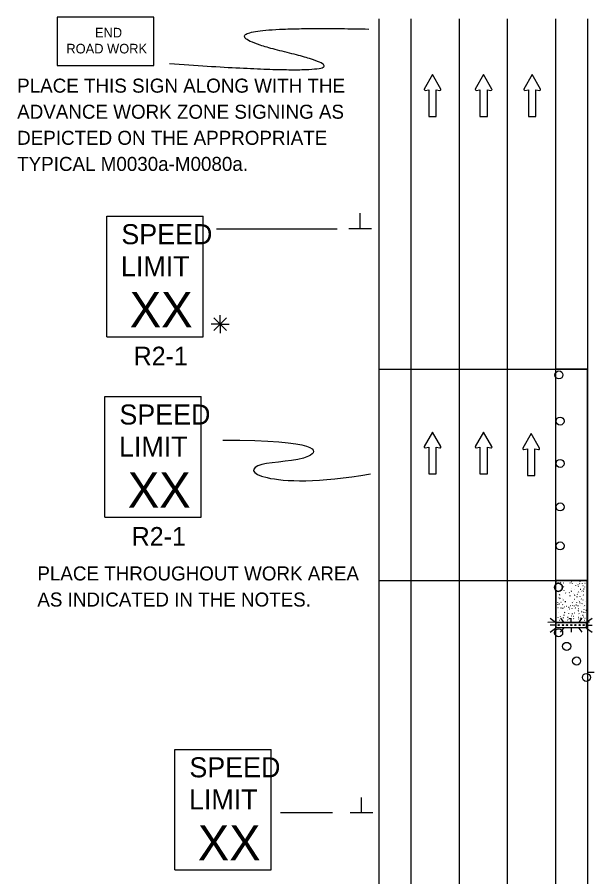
# Model space of a CAD drawing. Extents: x 16741 to 18479, y 6916 to 8211.
# Drawn here: x 16740.9 to 17027.6, y 7781.4 to 8209.8 of the extents above; entities that cross this region are included whole.
import ezdxf

# ---------------------------------------------------------------- set-up
doc = ezdxf.new("R2010")
doc.units = 0
for name, color, linetype in [('ALI_LEGAL_EX', 7, 'Continuous'), ('MT_SCRATCH_LEVEL_E', 7, 'Continuous'), ('PAVT_EDGE_EX', 7, 'Continuous'), ('TRAFFIC_SIGNS_PR', 7, 'Continuous'), ('TYPICAL_TEXT_DIMEN_PR', 7, 'Continuous')]:
    doc.layers.add(name, color=color, linetype=linetype)

msp = doc.modelspace()

# ---------------------------------------------------------------- linework, layer by layer
at = {"layer": 'ALI_LEGAL_EX'}
for p, q in [((16960.92, 8208.99), (16960.92, 7455.58)), ((16984.92, 8208.99), (16984.92, 7455.58))]:
    msp.add_line(p, q, dxfattribs=at)
for points in [[(16960.92, 8208.99), (16960.92, 8183.99)], [(16960.92, 8208.99), (16960.92, 8183.99)], [(16984.92, 8208.99), (16984.92, 8183.99)], [(16960.92, 8107.36), (16960.92, 8082.36)], [(16984.92, 8107.36), (16984.92, 8082.36)], [(16960.92, 8007.36), (16960.92, 7982.36)], [(16984.92, 8007.36), (16984.92, 7982.36)], [(16960.92, 7907.36), (16960.92, 7882.36)], [(16984.92, 7907.36), (16984.92, 7882.36)], [(16960.92, 7807.36), (16960.92, 7782.36)], [(16984.92, 7807.36), (16984.92, 7782.36)]]:
    msp.add_lwpolyline(points, dxfattribs=at)
at = {"layer": 'MT_SCRATCH_LEVEL_E'}
for p, q in [((16947.72, 8181.2), (16943.61, 8173.96)), ((16947.72, 8181.2), (16943.61, 8173.96)), ((16951.87, 8173.96), (16947.72, 8181.2)), ((16951.87, 8173.96), (16947.72, 8181.2)), ((16973.15, 8181.2), (16969.04, 8173.96)), ((16973.15, 8181.2), (16969.04, 8173.96)), ((16977.3, 8173.96), (16973.15, 8181.2)), ((16977.3, 8173.96), (16973.15, 8181.2)), ((16997.36, 8181.2), (16993.25, 8173.96)), ((16997.36, 8181.2), (16993.25, 8173.96)), ((17001.51, 8173.96), (16997.36, 8181.2)), ((17001.51, 8173.96), (16997.36, 8181.2)), ((16944.1, 8173.28), (16945.87, 8173.59)), ((16944.1, 8173.28), (16945.87, 8173.59)), ((16945.87, 8173.59), (16945.87, 8160.34)), ((16945.87, 8173.59), (16945.87, 8160.34)), ((16949.61, 8160.34), (16949.61, 8173.59)), ((16949.61, 8173.59), (16951.39, 8173.28)), ((16949.61, 8160.34), (16949.61, 8173.59)), ((16949.61, 8173.59), (16951.39, 8173.28)), ((16969.52, 8173.28), (16971.3, 8173.59)), ((16969.52, 8173.28), (16971.3, 8173.59)), ((16971.3, 8173.59), (16971.3, 8160.34)), ((16971.3, 8173.59), (16971.3, 8160.34)), ((16975.04, 8160.34), (16975.04, 8173.59)), ((16975.04, 8173.59), (16976.82, 8173.28)), ((16975.04, 8160.34), (16975.04, 8173.59)), ((16975.04, 8173.59), (16976.82, 8173.28)), ((16993.73, 8173.28), (16995.51, 8173.59)), ((16993.73, 8173.28), (16995.51, 8173.59)), ((16995.51, 8173.59), (16995.51, 8160.34)), ((16995.51, 8173.59), (16995.51, 8160.34)), ((16999.25, 8160.34), (16999.25, 8173.59)), ((16999.25, 8173.59), (17001.03, 8173.28)), ((16999.25, 8160.34), (16999.25, 8173.59)), ((16999.25, 8173.59), (17001.03, 8173.28)), ((16945.87, 8160.34), (16949.61, 8160.34)), ((16945.87, 8160.34), (16949.61, 8160.34)), ((16971.3, 8160.34), (16975.04, 8160.34)), ((16971.3, 8160.34), (16975.04, 8160.34)), ((16995.51, 8160.34), (16999.25, 8160.34)), ((16995.51, 8160.34), (16999.25, 8160.34)), ((16947.72, 8003.02), (16943.61, 7995.78)), ((16947.72, 8003.02), (16943.61, 7995.78)), ((16951.87, 7995.78), (16947.72, 8003.02)), ((16951.87, 7995.78), (16947.72, 8003.02)), ((16973.15, 8003.02), (16969.04, 7995.78)), ((16973.15, 8003.02), (16969.04, 7995.78)), ((16977.3, 7995.78), (16973.15, 8003.02)), ((16977.3, 7995.78), (16973.15, 8003.02)), ((16996.85, 8002.28), (16992.74, 7995.04)), ((16996.85, 8002.28), (16992.74, 7995.04)), ((17001, 7995.04), (16996.85, 8002.28)), ((17001, 7995.04), (16996.85, 8002.28)), ((16944.1, 7995.1), (16945.87, 7995.41)), ((16944.1, 7995.1), (16945.87, 7995.41)), ((16945.87, 7995.41), (16945.87, 7982.15)), ((16945.87, 7995.41), (16945.87, 7982.15)), ((16949.61, 7982.15), (16949.61, 7995.41)), ((16949.61, 7995.41), (16951.39, 7995.1)), ((16949.61, 7982.15), (16949.61, 7995.41)), ((16949.61, 7995.41), (16951.39, 7995.1)), ((16969.52, 7995.1), (16971.3, 7995.41)), ((16969.52, 7995.1), (16971.3, 7995.41)), ((16971.3, 7995.41), (16971.3, 7982.15)), ((16971.3, 7995.41), (16971.3, 7982.15)), ((16975.04, 7982.15), (16975.04, 7995.41)), ((16975.04, 7995.41), (16976.82, 7995.1)), ((16975.04, 7982.15), (16975.04, 7995.41)), ((16975.04, 7995.41), (16976.82, 7995.1)), ((16993.22, 7994.36), (16995, 7994.68)), ((16993.22, 7994.36), (16995, 7994.68)), ((16995, 7994.68), (16995, 7981.42)), ((16995, 7994.68), (16995, 7981.42)), ((16998.74, 7981.42), (16998.74, 7994.68)), ((16998.74, 7994.68), (17000.52, 7994.36)), ((16998.74, 7981.42), (16998.74, 7994.68)), ((16998.74, 7994.68), (17000.52, 7994.36)), ((16945.87, 7982.15), (16949.61, 7982.15)), ((16945.87, 7982.15), (16949.61, 7982.15)), ((16971.3, 7982.15), (16975.04, 7982.15)), ((16971.3, 7982.15), (16975.04, 7982.15)), ((16995, 7981.42), (16998.74, 7981.42)), ((16995, 7981.42), (16998.74, 7981.42))]:
    msp.add_line(p, q, dxfattribs=at)
for centre, start, end in [((16944.02, 8173.74), 150.4248, 279.9638), ((16944.02, 8173.74), 150.4248, 279.9638), ((16951.46, 8173.74), 260.0362, 29.7731), ((16951.46, 8173.74), 260.0362, 29.7731), ((16969.45, 8173.74), 150.4248, 279.9638), ((16969.45, 8173.74), 150.4248, 279.9638), ((16976.89, 8173.74), 260.0362, 29.7731), ((16976.89, 8173.74), 260.0362, 29.7731), ((16993.66, 8173.74), 150.4248, 279.9638), ((16993.66, 8173.74), 150.4248, 279.9638), ((17001.1, 8173.74), 260.0362, 29.7731), ((17001.1, 8173.74), 260.0362, 29.7731), ((16944.02, 7995.55), 150.4248, 279.9638), ((16944.02, 7995.55), 150.4248, 279.9638), ((16951.46, 7995.56), 260.0362, 29.7731), ((16951.46, 7995.56), 260.0362, 29.7731), ((16969.45, 7995.55), 150.4248, 279.9638), ((16969.45, 7995.55), 150.4248, 279.9638), ((16976.89, 7995.56), 260.0362, 29.7731), ((16976.89, 7995.56), 260.0362, 29.7731), ((16993.15, 7994.82), 150.4248, 279.9638), ((16993.15, 7994.82), 150.4248, 279.9638), ((17000.59, 7994.82), 260.0362, 29.7731), ((17000.59, 7994.82), 260.0362, 29.7731)]:
    msp.add_arc(centre, 0.463, start, end, dxfattribs=at)
at = {"layer": 'PAVT_EDGE_EX'}
for p, q in [((16920.92, 8208.99), (16920.92, 7354.26)), ((16936.92, 8208.99), (16936.92, 7354.26)), ((17008.92, 8208.99), (17008.92, 7354.26)), ((17024.92, 8208.99), (17024.92, 7354.26)), ((16921.45, 8034.32), (17024.92, 8034.32)), ((17024.92, 8034.32), (17008.92, 8034.32)), ((17008.92, 8034.32), (17008.92, 7929.01)), ((17024.92, 8034.32), (17008.92, 8034.32)), ((17008.92, 8034.32), (17008.92, 7929.01)), ((17024.92, 7929.01), (17024.92, 8034.32)), ((17024.92, 7929.01), (17024.92, 8034.32)), ((16921.45, 7929.01), (17024.92, 7929.01)), ((17008.92, 7929.01), (17024.92, 7929.01)), ((17008.92, 7929.01), (17024.92, 7929.01)), ((17028.22, 7883.18), (17024.92, 7883.18))]:
    msp.add_line(p, q, dxfattribs=at)
at = {"layer": 'TRAFFIC_SIGNS_PR'}
for p, q in [((16785.52, 8110.54), (16833.52, 8110.54)), ((16785.52, 8050.54), (16785.52, 8110.54)), ((16833.52, 8050.54), (16833.52, 8110.54)), ((16785.52, 8050.54), (16833.52, 8050.54)), ((16784.56, 8020.67), (16832.56, 8020.67)), ((16784.56, 7960.67), (16784.56, 8020.67)), ((16832.56, 7960.67), (16832.56, 8020.67)), ((16784.56, 7960.67), (16832.56, 7960.67)), ((17024.79, 7929.01), (17009.1, 7929.01)), ((17024.79, 7929.01), (17009.1, 7929.01)), ((17024.79, 7929.01), (17009.1, 7929.01)), ((17006.34, 7910.26), (17009.04, 7908.26)), ((17013.12, 7908.26), (17011.56, 7910.27)), ((17016.76, 7908.26), (17016.76, 7910.27)), ((17020.71, 7908.26), (17022.27, 7910.27)), ((17024.49, 7908.26), (17027.18, 7910.27)), ((17024.61, 7908.35), (17024.79, 7908.48)), ((17024.61, 7908.35), (17024.79, 7908.48)), ((17024.61, 7908.35), (17024.79, 7908.48)), ((17009.04, 7906.81), (17006.34, 7906.81)), ((17006.34, 7903.35), (17009.04, 7905.36)), ((17010.6, 7906.81), (17010.6, 7906.81)), ((17011.54, 7903.35), (17013.09, 7905.36)), ((17012.68, 7906.81), (17012.68, 7906.81)), ((17014.76, 7906.81), (17014.76, 7906.81)), ((17016.76, 7905.36), (17016.76, 7903.35)), ((17016.83, 7906.81), (17016.83, 7906.81)), ((17018.91, 7906.81), (17018.91, 7906.81)), ((17022.29, 7903.35), (17020.74, 7905.36)), ((17020.99, 7906.81), (17020.99, 7906.81)), ((17023.06, 7906.81), (17023.06, 7906.81)), ((17024.49, 7906.81), (17027.18, 7906.81)), ((17024.49, 7905.36), (17027.18, 7903.35)), ((16819.42, 7844.86), (16867.42, 7844.86)), ((16819.42, 7784.86), (16819.42, 7844.86)), ((16867.42, 7784.86), (16867.42, 7844.86)), ((16819.42, 7784.86), (16867.42, 7784.86))]:
    msp.add_line(p, q, dxfattribs=at)
for points in [[(16760.83, 8185.76), (16808.83, 8185.76), (16808.83, 8209.76), (16760.83, 8209.76)], [(17024.27, 7905.52), (17009.26, 7905.52), (17009.26, 7908.09), (17024.27, 7908.09)]]:
    msp.add_lwpolyline(points, close=True, dxfattribs=at)
for points in [[(17009.1, 7929.01), (17009.1, 7927.13)], [(17009.1, 7929.01), (17009.1, 7927.13)], [(17009.1, 7929.01), (17009.1, 7927.13)], [(17024.79, 7908.48), (17024.79, 7929.01)], [(17024.79, 7908.48), (17024.79, 7929.01)], [(17024.79, 7908.48), (17024.79, 7929.01)], [(17009.1, 7924.12), (17009.1, 7908.35), (17024.61, 7908.35)], [(17009.1, 7924.12), (17009.1, 7908.35), (17024.61, 7908.35)], [(17009.1, 7924.12), (17009.1, 7908.35)], [(17009.1, 7908.35), (17024.61, 7908.35)]]:
    msp.add_lwpolyline(points, dxfattribs=at)
for centre in [(17010.68, 8031.49), (17011.28, 8008.44), (17011.28, 7987.35), (17011.28, 7965.7), (17011.28, 7946.3), (17010.41, 7925.63), (17010.54, 7902.98), (17014.54, 7896.21), (17019.48, 7888.91), (17024.38, 7880.75)]:
    msp.add_circle(centre, 2, dxfattribs=at)
for start, end in [(43.6951, 131.0724), (43.6961, 131.0724), (43.6971, 131.0724), (0, 43.6931), (0.0007, 43.6931), (0.0007, 43.6931), (316.3077, 0), (316.3084, 0), (316.3084, 0), (228.9207, 316.3069), (228.9207, 316.3069), (228.9207, 316.3069), (228.9198, 240), (228.9207, 240.0001)]:
    msp.add_arc((17010.41, 7925.63), 2, start, end, dxfattribs=at)
for centre in [(17010.62, 7906.81), (17012.68, 7906.81), (17014.76, 7906.81), (17016.83, 7906.81), (17018.91, 7906.81), (17020.99, 7906.81), (17023.06, 7906.81)]:
    msp.add_ellipse(centre, major_axis=(0.362, 0), ratio=0.745879, dxfattribs=at)
msp.add_open_spline([(16816.7, 8186.66), (16931.92, 8178.42), (16818.01, 8206), (16915.96, 8203.84)], degree=2, dxfattribs=at)
at = {"layer": 'TYPICAL_TEXT_DIMEN_PR'}
for p, q in [((16911.63, 8104.3), (16911.63, 8112.08)), ((16840.05, 8104.31), (16900.3, 8104.31)), ((16911.63, 8104.3), (16906.01, 8104.3)), ((16917.26, 8104.3), (16911.63, 8104.3)), ((16838.77, 8059.95), (16845.15, 8053.57)), ((16845.15, 8059.95), (16838.77, 8053.57)), ((16841.96, 8056.76), (16841.96, 8061.22)), ((16841.96, 8056.76), (16837.43, 8056.76)), ((16841.96, 8056.76), (16845.15, 8056.76)), ((16841.96, 8056.76), (16846.44, 8056.76)), ((16841.96, 8056.76), (16841.96, 8052.26)), ((17024.79, 7929.01), (17009.1, 7929.01)), ((17010.06, 7928.08), (17010.27, 7928.03)), ((17011.47, 7928.14), (17011.68, 7928.08)), ((17011.57, 7927.22), (17011.52, 7927.32)), ((17011.95, 7927.68), (17011.9, 7927.78)), ((17012.98, 7927.88), (17013.2, 7927.83)), ((17013.04, 7925.94), (17012.98, 7926.05)), ((17016.24, 7927.68), (17016.18, 7927.78)), ((17016.78, 7925.13), (17016.72, 7925.23)), ((17016.78, 7928.29), (17017, 7928.24)), ((17017.43, 7927.57), (17017.38, 7927.68)), ((17019.16, 7926.45), (17019.11, 7926.56)), ((17019.6, 7927.68), (17019.54, 7927.78)), ((17020.09, 7927.01), (17020.3, 7926.96)), ((17020.36, 7926.1), (17020.3, 7926.2)), ((17021.01, 7927.42), (17020.95, 7927.52)), ((17021.12, 7928.49), (17021.33, 7928.44)), ((17022.42, 7927.62), (17022.36, 7927.73)), ((17022.53, 7926.56), (17022.74, 7926.5)), ((17023.5, 7927.73), (17023.72, 7927.68)), ((17023.61, 7925.79), (17023.56, 7925.89)), ((17010.33, 7922.02), (17010.27, 7922.12)), ((17010.98, 7921.92), (17011.3, 7922.07)), ((17013.36, 7924.06), (17013.31, 7924.16)), ((17014.07, 7922.78), (17014.01, 7922.88)), ((17015.75, 7922.99), (17015.97, 7922.94)), ((17016.13, 7921.41), (17016.45, 7921.56)), ((17016.78, 7923.7), (17017.1, 7923.85)), ((17017.92, 7922.68), (17017.86, 7922.78)), ((17018.51, 7921.66), (17018.84, 7921.81)), ((17018.62, 7924.52), (17018.57, 7924.62)), ((17019.54, 7921), (17019.54, 7920.69)), ((17019.76, 7922.17), (17019.98, 7922.12)), ((17020.25, 7923.34), (17020.47, 7923.29)), ((17021.06, 7922.83), (17021.01, 7922.94)), ((17021.28, 7920.9), (17021.22, 7921)), ((17021.33, 7924.72), (17021.55, 7924.67)), ((17022.2, 7923.8), (17022.15, 7923.9)), ((17022.63, 7921.51), (17022.58, 7921.61)), ((17022.85, 7921.86), (17023.07, 7921.81)), ((17022.96, 7924.92), (17023.18, 7924.87)), ((17023.01, 7923.5), (17022.96, 7923.6)), ((17010.11, 7918.14), (17010.06, 7918.24)), ((17010.11, 7917.07), (17010.06, 7917.17)), ((17010.6, 7917.33), (17010.92, 7917.48)), ((17010.76, 7920.34), (17010.71, 7920.44)), ((17011.14, 7920.03), (17011.46, 7920.18)), ((17011.74, 7918.04), (17011.68, 7918.14)), ((17012.39, 7917.02), (17012.6, 7916.97)), ((17012.49, 7919.98), (17012.44, 7920.08)), ((17012.98, 7919.21), (17012.93, 7919.32)), ((17013.96, 7918.3), (17013.96, 7918.76)), ((17016.4, 7916.61), (17016.62, 7916.56)), ((17017.27, 7917.99), (17017.48, 7917.94)), ((17017.92, 7918.35), (17017.86, 7918.45)), ((17018.19, 7919.72), (17018.41, 7919.67)), ((17019.17, 7916.92), (17019.38, 7916.87)), ((17019.65, 7917.89), (17019.6, 7917.99)), ((17020.09, 7916.46), (17020.41, 7916.61)), ((17020.63, 7919.16), (17020.57, 7919.27)), ((17020.9, 7918.65), (17021.12, 7918.6)), ((17021.06, 7917.94), (17021.28, 7917.89)), ((17021.6, 7916.51), (17021.55, 7916.61)), ((17021.77, 7919.82), (17021.99, 7919.77)), ((17022.04, 7917.63), (17022.04, 7917.33)), ((17022.42, 7917.17), (17022.36, 7917.28)), ((17022.8, 7919.27), (17022.74, 7919.37)), ((17024.1, 7918.35), (17024.04, 7918.45)), ((17010.22, 7915.34), (17010.16, 7915.44)), ((17010.27, 7912.89), (17010.22, 7912.99)), ((17011.63, 7915.49), (17011.85, 7915.44)), ((17011.79, 7915.29), (17011.74, 7915.39)), ((17012.5, 7915.24), (17012.71, 7915.19)), ((17013.42, 7915.8), (17013.36, 7915.9)), ((17013.42, 7913.05), (17013.74, 7913.2)), ((17014.56, 7916), (17014.5, 7916.1)), ((17015.15, 7914.22), (17015.1, 7914.32)), ((17015.53, 7915.8), (17015.75, 7915.75)), ((17015.69, 7912.43), (17015.64, 7912.53)), ((17015.91, 7914.73), (17015.86, 7914.83)), ((17017.27, 7914.93), (17017.21, 7915.03)), ((17017.32, 7912.53), (17017.32, 7912.23)), ((17017.65, 7916.41), (17017.59, 7916.51)), ((17018.4, 7916.31), (17018.35, 7916.41)), ((17018.41, 7912.94), (17018.62, 7912.89)), ((17019, 7915.24), (17018.84, 7915.34)), ((17018.89, 7915.19), (17018.84, 7915.29)), ((17020.19, 7913.91), (17020.52, 7914.06)), ((17020.41, 7915.08), (17020.63, 7915.03)), ((17020.58, 7912.53), (17020.79, 7912.48)), ((17021.98, 7913.56), (17021.98, 7913.25)), ((17022.09, 7913.86), (17022.04, 7913.96)), ((17022.74, 7916.05), (17022.69, 7916.15)), ((17022.85, 7913.3), (17023.07, 7913.25)), ((17023.28, 7914.57), (17023.23, 7914.68)), ((17023.5, 7916.41), (17023.45, 7916.51)), ((17023.72, 7912.94), (17023.67, 7913.05)), ((17024.1, 7914.22), (17024.32, 7914.17)), ((17025.91, 7908.21), (17005.21, 7908.18)), ((17010.38, 7910.5), (17010.33, 7910.6)), ((17011.08, 7909.02), (17011.03, 7909.12)), ((17011.41, 7910.95), (17011.36, 7911.06)), ((17012.71, 7910.55), (17012.71, 7910.24)), ((17013.09, 7911.98), (17013.09, 7911.67)), ((17014.88, 7909.38), (17015.1, 7909.32)), ((17014.99, 7910.75), (17015.21, 7910.7)), ((17015.8, 7909.78), (17015.75, 7909.88)), ((17015.97, 7910.29), (17015.97, 7909.99)), ((17016.89, 7911.21), (17016.83, 7911.31)), ((17017.86, 7911.26), (17018.08, 7911.21)), ((17018.03, 7909.99), (17017.97, 7910.09)), ((17020.19, 7910.75), (17020.41, 7910.7)), ((17020.57, 7909.78), (17020.52, 7909.88)), ((17021.33, 7910.39), (17021.55, 7910.34)), ((17021.6, 7911.52), (17021.55, 7911.62)), ((17022.47, 7911.77), (17022.69, 7911.72)), ((17022.85, 7910.9), (17023.07, 7910.85)), ((17023.18, 7909.32), (17023.4, 7909.27)), ((17023.67, 7910.04), (17023.61, 7910.14)), ((17024.61, 7908.35), (17024.79, 7908.48)), ((16912.31, 7813.18), (16912.31, 7820.97)), ((16897.92, 7813.18), (16871.92, 7813.18)), ((16912.31, 7813.18), (16906.68, 7813.18)), ((16917.93, 7813.18), (16912.31, 7813.18))]:
    msp.add_line(p, q, dxfattribs=at)
for points in [[(17009.1, 7929.01), (17009.1, 7927.13)], [(17024.79, 7908.48), (17024.79, 7929.01)], [(17009.1, 7924.12), (17009.1, 7908.35)], [(17009.1, 7908.35), (17024.61, 7908.35)]]:
    msp.add_lwpolyline(points, dxfattribs=at)
for start, end in [(43.6941, 131.0793), (0, 43.6931), (316.3059, 0), (228.9207, 316.3069), (228.9198, 240), (228.9207, 240.0001)]:
    msp.add_arc((17010.41, 7925.63), 2, start, end, dxfattribs=at)
msp.add_open_spline([(16843.25, 7999.03), (16891.72, 7999.03), (16891.72, 7988.28), (16856.8, 7988.28), (16856.8, 7979.23), (16891.01, 7977.47), (16916.78, 7982.24)], degree=3, dxfattribs=at)

# ---------------------------------------------------------------- texts
at = {"layer": 'TRAFFIC_SIGNS_PR'}
for s, height, p in [('END', 4.789, (16779.58, 8199.67)), ('ROAD WORK', 4.789, (16765.34, 8191.69)), ('PLACE THIS SIGN ALONG WITH THE', 7, (16740.83, 8172.14)), ('ADVANCE WORK ZONE SIGNING AS', 7, (16740.83, 8159.14)), ('DEPICTED ON THE APPROPRIATE', 7, (16740.83, 8146.14)), ('TYPICAL M0030a-M0080a.', 7, (16740.83, 8133.14)), ('SPEED', 10, (16792.73, 8096.62)), ('LIMIT', 10, (16792.53, 8080.62)), ('XX', 17.538, (16796.91, 8055.24)), ('R2-1', 9.3, (16798.87, 8036.25)), ('SPEED', 10, (16791.76, 8006.75)), ('LIMIT', 10, (16791.56, 7990.75)), ('XX', 17.538, (16795.95, 7965.37)), ('R2-1', 9.3, (16797.9, 7946.37)), ('PLACE THROUGHOUT WORK AREA', 7, (16750.89, 7929.05)), ('AS INDICATED IN THE NOTES.', 7, (16750.89, 7916.05)), ('SPEED', 10, (16826.62, 7830.94)), ('LIMIT', 10, (16826.42, 7814.94)), ('XX', 17.538, (16830.81, 7789.56))]:
    msp.add_text(s, height=height, dxfattribs=at).set_placement(p)

doc.saveas('drawing.dxf')
